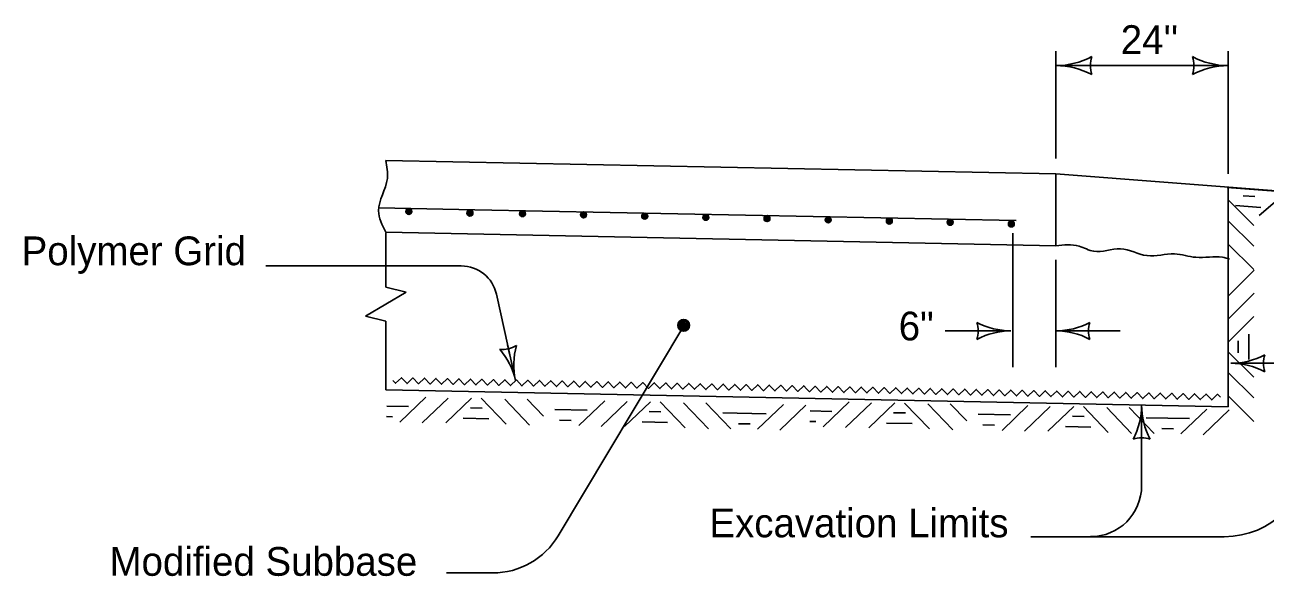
# Model space of a CAD drawing. Extents: x 5546 to 81668, y 3174 to 15999.
# Drawn here: x 17301 to 17992, y 13163 to 13470 of the extents above; entities that cross this region are included whole.
import ezdxf

# ---------------------------------------------------------------- set-up
doc = ezdxf.new("R2010")
doc.units = 0
for name, color, linetype in [('PS_CONST', 7, 'Continuous'), ('PS_DAWA', 7, 'Continuous'), ('PS_DIM', 7, 'Continuous')]:
    doc.layers.add(name, color=color, linetype=linetype)

msp = doc.modelspace()

# ---------------------------------------------------------------- linework, layer by layer
at = {"layer": 'PS_CONST'}
for p, q in [((17435.53, 13335.55), (17544.32, 13335.55)), ((17563.85, 13319.86), (17574.46, 13271.73)), ((17598.32, 13185.41), (17668.13, 13302.18)), ((17997.4, 13281.41), (17972.68, 13281.41)), ((17923, 13258.09), (17923, 13213.24)), ((17969.04, 13184.87), (17861.27, 13184.87)), ((17536.04, 13164.7), (17561.8, 13164.7))]:
    msp.add_line(p, q, dxfattribs=at)
msp.add_lwpolyline([(17667.85, 13299.47), (17668.97, 13299.97), (17670.7, 13300.51), (17671.04, 13302.27), (17670.8, 13303.82), (17669.69, 13305.25), (17668.04, 13305.1), (17666.3, 13304.85), (17665.46, 13303.47), (17665.31, 13302), (17666.33, 13300.09), (17667.61, 13299.93), (17669.34, 13300.37), (17670.77, 13301.48), (17670.73, 13303.14), (17669.61, 13304.47), (17668.05, 13304.61), (17666.31, 13304.27), (17666.05, 13303.29), (17665.7, 13302.11), (17666.51, 13300.68), (17667.78, 13300.72), (17669.23, 13300.95), (17670.28, 13301.76), (17669.75, 13303.2), (17668.65, 13304.05), (17667.19, 13304.1), (17666.83, 13303.32), (17666.36, 13302.43), (17667.08, 13301.28), (17668.16, 13301.02), (17669.12, 13301.53), (17669.18, 13302.6), (17668.68, 13303.37), (17667.69, 13303.63), (17667.22, 13303.23), (17666.94, 13302.64), (17667.45, 13301.78), (17668.14, 13301.6), (17668.81, 13302.01), (17668.7, 13302.59), (17668.2, 13302.96), (17667.52, 13302.94), (17667.53, 13302.46), (17668.13, 13302.18)], dxfattribs=at)
msp.add_circle((17668.11, 13302.51), 3.31, dxfattribs=at)
for centre, radius, start, end in [((17544.32, 13315.55), 20, 12.43134, 90), ((17567.22, 13304.63), 15.52, 264.68499, 300.15169), ((17613.7, 13280.37), 40.18, 164.34585, 192.41834), ((17535.23, 13263.09), 40.18, 12.41834, 40.49083), ((17972.68, 13321.58), 40.18, 270, 298.07249), ((18006.37, 13281.41), 15.52, 162.26665, 197.73335), ((17972.68, 13241.23), 40.18, 61.92751, 90), ((17882.82, 13258.09), 40.18, 331.92751, 360), ((17963.17, 13258.09), 40.18, 180, 208.07249), ((17923, 13224.41), 15.52, 72.26665, 107.73335), ((17969.04, 13232.14), 47.27, 270, 360), ((17894.64, 13213.24), 28.36, 270, 360), ((17561.8, 13207.24), 42.54, 270, 329.12488)]:
    msp.add_arc(centre, radius, start, end, dxfattribs=at)
at = {"layer": 'PS_DAWA'}
for p, q in [((17875.27, 13395.36), (17875.27, 13455.07)), ((17971.27, 13386.8), (17971.27, 13455.07)), ((17875.27, 13447.09), (17971.27, 13447.09)), ((17851.27, 13279.25), (17851.27, 13353.72)), ((17875.27, 13279.25), (17875.27, 13338.95)), ((17850.28, 13299.44), (17813.74, 13299.44)), ((17911.05, 13299.44), (17875.27, 13299.44))]:
    msp.add_line(p, q, dxfattribs=at)
for centre, radius, start, end in [((17875.27, 13489.59), 42.5, 270, 298.07249), ((17910.9, 13447.09), 16.42, 162.26665, 197.73335), ((17935.63, 13447.09), 16.42, 342.26665, 17.73335), ((17971.27, 13489.59), 42.5, 241.92751, 270), ((17875.27, 13404.59), 42.5, 61.92751, 90), ((17971.27, 13404.59), 42.5, 90, 118.07249), ((17816.59, 13299.43), 15.52, 342.26665, 17.73335), ((17850.28, 13339.61), 40.18, 241.92751, 270), ((17850.28, 13259.26), 40.18, 90, 118.07249), ((17875.27, 13339.61), 40.18, 270, 298.07249), ((17875.27, 13259.26), 40.18, 61.92751, 90), ((17908.95, 13299.44), 15.52, 162.26665, 197.73335)]:
    msp.add_arc(centre, radius, start, end, dxfattribs=at)
at = {"layer": 'PS_DIM'}
for p, q in [((17875.27, 13386.8), (17502.34, 13394.29)), ((17502.34, 13394.29), (17875.27, 13386.8)), ((17875.27, 13346.79), (17875.27, 13386.8)), ((17875.27, 13386.8), (17875.27, 13346.79)), ((17875.27, 13386.8), (18074.73, 13371.45)), ((17970.65, 13379.22), (18074.12, 13371.26)), ((17971.27, 13257.15), (17971.27, 13379.41)), ((18003.56, 13376.69), (17988.38, 13363.67)), ((17551.81, 13366.85), (17498.37, 13367.92)), ((17853.17, 13360.8), (17551.81, 13366.85)), ((17971.27, 13372.31), (17985.41, 13358.16)), ((17971.27, 13360.73), (17985.41, 13346.59)), ((17502.34, 13354.28), (17875.27, 13346.79)), ((17502.34, 13354.28), (17875.27, 13346.79)), ((17502.34, 13354.02), (17502.34, 13323.76)), ((17971.27, 13347.67), (17985.41, 13333.53)), ((17971.49, 13319.14), (17985.64, 13333.28)), ((17502.34, 13323.76), (17513.68, 13320.92)), ((17513.68, 13320.92), (17502.34, 13314.31)), ((17971.49, 13306.23), (17985.64, 13320.38)), ((17502.34, 13314.31), (17490.99, 13307.69)), ((17490.99, 13307.69), (17502.34, 13304.85)), ((17502.34, 13304.85), (17502.34, 13266.54)), ((17971.27, 13293.23), (17985.41, 13307.37)), ((17570.07, 13291.65), (17571.2, 13286.54)), ((17971.27, 13287.81), (17985.41, 13273.67)), ((17971.27, 13276.24), (17985.41, 13262.1)), ((17502.34, 13266.54), (17971.26, 13257.12)), ((17971.27, 13263.18), (17985.41, 13249.04)), ((17524.61, 13262.52), (17510.19, 13248.67)), ((17537.05, 13262.04), (17522.63, 13248.19)), ((17550.06, 13262.01), (17535.64, 13248.15)), ((17555.47, 13261.9), (17569.33, 13247.48)), ((17568.47, 13261.41), (17582.33, 13246.99)), ((17580.93, 13261.39), (17590.03, 13251.92)), ((17624.14, 13260.52), (17609.72, 13246.67)), ((17636.58, 13260.05), (17622.16, 13246.19)), ((17649.59, 13260.01), (17635.17, 13246.16)), ((17655, 13259.9), (17668.86, 13245.48)), ((17668.01, 13259.42), (17681.86, 13244.99)), ((17680.46, 13259.39), (17694.31, 13244.97)), ((17723.67, 13258.53), (17709.25, 13244.67)), ((17736.12, 13258.05), (17721.69, 13244.19)), ((17760.21, 13259.88), (17745.79, 13246.03)), ((17772.65, 13259.41), (17758.23, 13245.55)), ((17785.66, 13259.37), (17771.24, 13245.52)), ((17791.07, 13259.26), (17804.93, 13244.84)), ((17804.08, 13258.78), (17817.93, 13244.35)), ((17816.53, 13258.75), (17825.63, 13249.28)), ((17859.74, 13257.89), (17845.32, 13244.03)), ((17872.19, 13257.41), (17857.76, 13243.55)), ((17885.2, 13257.38), (17870.77, 13243.52)), ((17890.61, 13257.27), (17904.46, 13242.84)), ((17903.61, 13256.78), (17917.46, 13242.36)), ((17916.06, 13256.76), (17929.92, 13242.33)), ((17959.28, 13255.89), (17944.85, 13242.03)), ((17971.72, 13255.41), (17957.3, 13241.56))]:
    msp.add_line(p, q, dxfattribs=at)
for points in [[(17979.57, 13374.68), (17986.09, 13374.18)], [(17513.59, 13365.79), (17513.84, 13366.36), (17514.11, 13367.22), (17514.99, 13367.39), (17515.76, 13367.27), (17516.48, 13366.71), (17516.4, 13365.89), (17516.28, 13365.02), (17515.59, 13364.6), (17514.86, 13364.52), (17513.9, 13365.04), (17513.82, 13365.67), (17514.04, 13366.54), (17514.6, 13367.26), (17515.42, 13367.23), (17516.09, 13366.68), (17516.16, 13365.9), (17515.99, 13365.03), (17515.5, 13364.89), (17514.91, 13364.72), (17514.19, 13365.12), (17514.21, 13365.76), (17514.33, 13366.48), (17514.73, 13367.01), (17515.46, 13366.74), (17515.88, 13366.2), (17515.9, 13365.47), (17515.51, 13365.28), (17515.07, 13365.05), (17514.49, 13365.41), (17514.36, 13365.95), (17514.62, 13366.43), (17515.16, 13366.46), (17515.54, 13366.21), (17515.67, 13365.71), (17515.47, 13365.48), (17515.17, 13365.34), (17514.74, 13365.59), (17514.66, 13365.94), (17514.86, 13366.27), (17515.15, 13366.22), (17515.34, 13365.97), (17515.33, 13365.63), (17515.08, 13365.63), (17514.95, 13365.93)], [(17547.62, 13364.87), (17547.87, 13365.42), (17548.14, 13366.3), (17549.02, 13366.46), (17549.79, 13366.34), (17550.51, 13365.79), (17550.44, 13364.96), (17550.31, 13364.09), (17549.62, 13363.67), (17548.89, 13363.59), (17547.93, 13364.11), (17547.85, 13364.74), (17548.07, 13365.62), (17548.63, 13366.32), (17549.45, 13366.3), (17550.12, 13365.75), (17550.19, 13364.97), (17550.02, 13364.1), (17549.53, 13363.97), (17548.94, 13363.79), (17548.23, 13364.2), (17548.24, 13364.83), (17548.36, 13365.56), (17548.77, 13366.08), (17549.49, 13365.82), (17549.91, 13365.27), (17549.94, 13364.54), (17549.54, 13364.35), (17549.1, 13364.12), (17548.52, 13364.48), (17548.4, 13365.02), (17548.65, 13365.5), (17549.19, 13365.53), (17549.57, 13365.28), (17549.7, 13364.79), (17549.5, 13364.55), (17549.2, 13364.41), (17548.77, 13364.67), (17548.69, 13365.01), (17548.89, 13365.35), (17549.18, 13365.29), (17549.37, 13365.04), (17549.36, 13364.7), (17549.11, 13364.7), (17548.98, 13365)], [(17975.3, 13369.13), (17989.45, 13368.04)], [(17579.88, 13364.53), (17579.63, 13365.1), (17579.36, 13365.96), (17578.48, 13366.13), (17577.71, 13366.01), (17576.99, 13365.45), (17577.06, 13364.63), (17577.18, 13363.76), (17577.88, 13363.34), (17578.61, 13363.26), (17579.57, 13363.78), (17579.65, 13364.42), (17579.43, 13365.28), (17578.87, 13366), (17578.05, 13365.97), (17577.38, 13365.42), (17577.31, 13364.64), (17577.47, 13363.77), (17577.97, 13363.63), (17578.56, 13363.46), (17579.27, 13363.87), (17579.26, 13364.5), (17579.14, 13365.23), (17578.73, 13365.75), (17578.01, 13365.48), (17577.59, 13364.94), (17577.56, 13364.21), (17577.96, 13364.02), (17578.4, 13363.8), (17578.98, 13364.15), (17579.1, 13364.69), (17578.85, 13365.17), (17578.31, 13365.2), (17577.93, 13364.95), (17577.8, 13364.46), (17578, 13364.22), (17578.3, 13364.08), (17578.72, 13364.34), (17578.81, 13364.68), (17578.61, 13365.02), (17578.32, 13364.96), (17578.13, 13364.71), (17578.14, 13364.37), (17578.39, 13364.38), (17578.52, 13364.67)], [(17613.91, 13363.86), (17613.66, 13364.41), (17613.39, 13365.28), (17612.51, 13365.45), (17611.74, 13365.33), (17611.02, 13364.77), (17611.1, 13363.95), (17611.21, 13363.08), (17611.91, 13362.66), (17612.64, 13362.58), (17613.6, 13363.09), (17613.68, 13363.73), (17613.46, 13364.6), (17612.9, 13365.32), (17612.08, 13365.29), (17611.41, 13364.74), (17611.34, 13363.95), (17611.51, 13363.09), (17612, 13362.95), (17612.59, 13362.78), (17613.31, 13363.18), (17613.28, 13363.82), (17613.17, 13364.54), (17612.77, 13365.07), (17612.04, 13364.8), (17611.62, 13364.25), (17611.59, 13363.52), (17611.98, 13363.34), (17612.43, 13363.11), (17613.01, 13363.47), (17613.13, 13364.01), (17612.88, 13364.49), (17612.34, 13364.52), (17611.96, 13364.27), (17611.83, 13363.77), (17612.03, 13363.54), (17612.33, 13363.4), (17612.76, 13363.65), (17612.84, 13364), (17612.64, 13364.33), (17612.35, 13364.28), (17612.16, 13364.03), (17612.17, 13363.69), (17612.42, 13363.69), (17612.55, 13363.99)], [(17647.94, 13363.17), (17647.69, 13363.73), (17647.42, 13364.6), (17646.54, 13364.77), (17645.77, 13364.65), (17645.05, 13364.09), (17645.13, 13363.26), (17645.25, 13362.39), (17645.94, 13361.97), (17646.67, 13361.9), (17647.63, 13362.41), (17647.71, 13363.05), (17647.49, 13363.92), (17646.94, 13364.63), (17646.11, 13364.61), (17645.44, 13364.05), (17645.37, 13363.27), (17645.54, 13362.4), (17646.03, 13362.27), (17646.62, 13362.09), (17647.34, 13362.5), (17647.32, 13363.13), (17647.2, 13363.86), (17646.8, 13364.39), (17646.08, 13364.12), (17645.65, 13363.57), (17645.63, 13362.84), (17646.02, 13362.66), (17646.47, 13362.43), (17647.04, 13362.79), (17647.17, 13363.33), (17646.91, 13363.8), (17646.38, 13363.84), (17645.99, 13363.58), (17645.86, 13363.09), (17646.06, 13362.85), (17646.36, 13362.72), (17646.79, 13362.97), (17646.88, 13363.32), (17646.67, 13363.65), (17646.38, 13363.59), (17646.2, 13363.35), (17646.2, 13363), (17646.45, 13363.01), (17646.58, 13363.31)], [(17681.98, 13362.49), (17681.72, 13363.04), (17681.46, 13363.91), (17680.58, 13364.08), (17679.8, 13363.96), (17679.09, 13363.41), (17679.16, 13362.58), (17679.28, 13361.71), (17679.97, 13361.29), (17680.71, 13361.21), (17681.66, 13361.73), (17681.75, 13362.36), (17681.52, 13363.24), (17680.97, 13363.95), (17680.14, 13363.92), (17679.48, 13363.37), (17679.4, 13362.59), (17679.57, 13361.72), (17680.07, 13361.58), (17680.65, 13361.41), (17681.37, 13361.82), (17681.35, 13362.45), (17681.24, 13363.18), (17680.83, 13363.7), (17680.11, 13363.44), (17679.68, 13362.89), (17679.66, 13362.16), (17680.05, 13361.97), (17680.5, 13361.74), (17681.07, 13362.1), (17681.2, 13362.64), (17680.95, 13363.12), (17680.41, 13363.15), (17680.03, 13362.9), (17679.89, 13362.41), (17680.09, 13362.17), (17680.39, 13362.03), (17680.82, 13362.29), (17680.91, 13362.63), (17680.71, 13362.97), (17680.42, 13362.91), (17680.23, 13362.66), (17680.24, 13362.32), (17680.48, 13362.33), (17680.62, 13362.62)], [(17716.01, 13361.8), (17715.76, 13362.36), (17715.49, 13363.23), (17714.61, 13363.4), (17713.84, 13363.28), (17713.12, 13362.72), (17713.19, 13361.9), (17713.32, 13361.02), (17714.01, 13360.61), (17714.74, 13360.53), (17715.7, 13361.05), (17715.78, 13361.68), (17715.56, 13362.55), (17715, 13363.26), (17714.18, 13363.24), (17713.51, 13362.68), (17713.44, 13361.91), (17713.6, 13361.03), (17714.1, 13360.9), (17714.69, 13360.73), (17715.4, 13361.14), (17715.39, 13361.76), (17715.27, 13362.5), (17714.86, 13363.02), (17714.14, 13362.75), (17713.72, 13362.2), (17713.69, 13361.47), (17714.09, 13361.29), (17714.53, 13361.06), (17715.11, 13361.42), (17715.23, 13361.96), (17714.98, 13362.44), (17714.44, 13362.47), (17714.06, 13362.22), (17713.93, 13361.73), (17714.13, 13361.49), (17714.43, 13361.35), (17714.86, 13361.61), (17714.94, 13361.95), (17714.74, 13362.28), (17714.45, 13362.23), (17714.26, 13361.98), (17714.27, 13361.64), (17714.52, 13361.64), (17714.65, 13361.94)], [(17750.04, 13361.12), (17749.79, 13361.68), (17749.52, 13362.55), (17748.64, 13362.72), (17747.87, 13362.6), (17747.15, 13362.04), (17747.23, 13361.21), (17747.35, 13360.34), (17748.04, 13359.93), (17748.77, 13359.85), (17749.73, 13360.36), (17749.81, 13361), (17749.59, 13361.87), (17749.03, 13362.58), (17748.21, 13362.56), (17747.54, 13362), (17747.47, 13361.22), (17747.64, 13360.35), (17748.13, 13360.22), (17748.72, 13360.04), (17749.44, 13360.45), (17749.42, 13361.08), (17749.3, 13361.81), (17748.9, 13362.34), (17748.17, 13362.07), (17747.75, 13361.52), (17747.73, 13360.79), (17748.12, 13360.61), (17748.56, 13360.38), (17749.14, 13360.73), (17749.26, 13361.27), (17749.01, 13361.76), (17748.47, 13361.79), (17748.09, 13361.53), (17747.96, 13361.04), (17748.16, 13360.8), (17748.46, 13360.67), (17748.89, 13360.92), (17748.97, 13361.27), (17748.77, 13361.6), (17748.48, 13361.54), (17748.29, 13361.29), (17748.3, 13360.96), (17748.55, 13360.96), (17748.68, 13361.26)], [(17784.07, 13360.44), (17783.82, 13360.99), (17783.55, 13361.86), (17782.67, 13362.03), (17781.9, 13361.91), (17781.18, 13361.36), (17781.26, 13360.53), (17781.38, 13359.66), (17782.07, 13359.24), (17782.8, 13359.16), (17783.76, 13359.68), (17783.84, 13360.31), (17783.62, 13361.19), (17783.07, 13361.9), (17782.24, 13361.88), (17781.58, 13361.32), (17781.5, 13360.54), (17781.67, 13359.67), (17782.16, 13359.54), (17782.75, 13359.36), (17783.47, 13359.77), (17783.45, 13360.4), (17783.33, 13361.13), (17782.93, 13361.65), (17782.21, 13361.39), (17781.78, 13360.84), (17781.76, 13360.11), (17782.15, 13359.93), (17782.6, 13359.69), (17783.17, 13360.05), (17783.3, 13360.59), (17783.04, 13361.07), (17782.51, 13361.11), (17782.12, 13360.85), (17781.99, 13360.36), (17782.19, 13360.12), (17782.49, 13359.98), (17782.92, 13360.24), (17783.01, 13360.58), (17782.8, 13360.92), (17782.51, 13360.86), (17782.33, 13360.61), (17782.33, 13360.27), (17782.58, 13360.28), (17782.71, 13360.58)], [(17814.95, 13359.75), (17815.2, 13360.31), (17815.47, 13361.17), (17816.35, 13361.34), (17817.12, 13361.22), (17817.84, 13360.67), (17817.76, 13359.84), (17817.64, 13358.97), (17816.95, 13358.55), (17816.22, 13358.47), (17815.26, 13358.99), (17815.18, 13359.62), (17815.4, 13360.49), (17815.96, 13361.21), (17816.78, 13361.18), (17817.45, 13360.63), (17817.52, 13359.85), (17817.35, 13358.98), (17816.86, 13358.84), (17816.27, 13358.67), (17815.55, 13359.07), (17815.57, 13359.71), (17815.69, 13360.43), (17816.09, 13360.96), (17816.81, 13360.7), (17817.24, 13360.15), (17817.26, 13359.42), (17816.87, 13359.23), (17816.43, 13359), (17815.85, 13359.36), (17815.72, 13359.9), (17815.98, 13360.38), (17816.52, 13360.41), (17816.9, 13360.16), (17817.03, 13359.67), (17816.83, 13359.43), (17816.53, 13359.29), (17816.1, 13359.55), (17816.02, 13359.89), (17816.22, 13360.22), (17816.51, 13360.17), (17816.69, 13359.92), (17816.68, 13359.58), (17816.44, 13359.59), (17816.31, 13359.88)], [(17848.98, 13358.82), (17849.23, 13359.38), (17849.5, 13360.25), (17850.38, 13360.41), (17851.15, 13360.29), (17851.87, 13359.74), (17851.8, 13358.91), (17851.67, 13358.04), (17850.98, 13357.62), (17850.25, 13357.54), (17849.29, 13358.06), (17849.21, 13358.69), (17849.43, 13359.57), (17849.99, 13360.28), (17850.81, 13360.25), (17851.48, 13359.7), (17851.55, 13358.92), (17851.38, 13358.05), (17850.89, 13357.92), (17850.3, 13357.74), (17849.58, 13358.15), (17849.6, 13358.78), (17849.72, 13359.51), (17850.13, 13360.03), (17850.85, 13359.77), (17851.27, 13359.22), (17851.3, 13358.49), (17850.9, 13358.31), (17850.46, 13358.07), (17849.88, 13358.43), (17849.76, 13358.97), (17850.01, 13359.45), (17850.55, 13359.48), (17850.93, 13359.23), (17851.06, 13358.74), (17850.86, 13358.5), (17850.56, 13358.36), (17850.13, 13358.62), (17850.05, 13358.96), (17850.25, 13359.3), (17850.54, 13359.24), (17850.73, 13358.99), (17850.72, 13358.65), (17850.47, 13358.66), (17850.34, 13358.95)], [(17982.62, 13283.42), (17982.62, 13297.62)], [(17976.77, 13287.25), (17976.77, 13293.79)], [(17506.15, 13271.87), (17507.72, 13270.23), (17510.98, 13273.37), (17514.12, 13270.11), (17517.38, 13273.24), (17520.52, 13269.98), (17523.78, 13273.11), (17526.91, 13269.85), (17530.18, 13272.98), (17533.31, 13269.72), (17536.58, 13272.86), (17539.71, 13269.59), (17542.98, 13272.73), (17546.11, 13269.46), (17549.37, 13272.6), (17552.51, 13269.34), (17555.77, 13272.47), (17558.91, 13269.21), (17562.17, 13272.34), (17565.31, 13269.08), (17568.57, 13272.21), (17571.71, 13268.95), (17574.97, 13272.09), (17578.1, 13268.82), (17581.37, 13271.96), (17582.94, 13270.33)], [(17582.94, 13270.33), (17584.5, 13268.69), (17587.77, 13271.83), (17590.9, 13268.56), (17594.16, 13271.7), (17597.3, 13268.44), (17600.56, 13271.57), (17603.7, 13268.31), (17606.96, 13271.44), (17610.1, 13268.18), (17613.36, 13271.31), (17616.5, 13268.05), (17619.76, 13271.19), (17622.89, 13267.92), (17626.16, 13271.06), (17629.29, 13267.79), (17632.56, 13270.93), (17635.69, 13267.67), (17638.96, 13270.8), (17642.09, 13267.54), (17645.35, 13270.67), (17648.49, 13267.41), (17651.75, 13270.54), (17654.89, 13267.28), (17658.15, 13270.42), (17659.72, 13268.78)], [(17659.72, 13268.78), (17661.29, 13267.15), (17664.55, 13270.29), (17667.69, 13267.02), (17670.95, 13270.16), (17674.08, 13266.9), (17677.35, 13270.03), (17680.48, 13266.77), (17683.75, 13269.9), (17686.88, 13266.64), (17690.15, 13269.77), (17693.28, 13266.51), (17696.54, 13269.64), (17699.68, 13266.38), (17702.94, 13269.52), (17706.08, 13266.25), (17709.34, 13269.39), (17712.48, 13266.12), (17715.74, 13269.26), (17718.88, 13266), (17722.14, 13269.13), (17725.27, 13265.87), (17728.54, 13269), (17731.67, 13265.74), (17734.94, 13268.87), (17736.5, 13267.24)], [(17736.54, 13267.14), (17738.11, 13265.51), (17741.37, 13268.64), (17744.5, 13265.38), (17747.77, 13268.52), (17750.9, 13265.25), (17754.17, 13268.39), (17757.3, 13265.12), (17760.57, 13268.26), (17763.7, 13265), (17766.96, 13268.13), (17770.1, 13264.87), (17773.36, 13268), (17776.5, 13264.74), (17779.76, 13267.87), (17782.9, 13264.61), (17786.16, 13267.75), (17789.3, 13264.48), (17792.56, 13267.62), (17795.69, 13264.35), (17798.96, 13267.49), (17802.09, 13264.23), (17805.36, 13267.36), (17808.49, 13264.1), (17811.76, 13267.23), (17813.32, 13265.6)], [(17813.32, 13265.6), (17814.89, 13263.97), (17818.15, 13267.1), (17821.29, 13263.84), (17824.55, 13266.98), (17827.69, 13263.71), (17830.95, 13266.85), (17834.09, 13263.58), (17837.35, 13266.72), (17840.49, 13263.45), (17843.75, 13266.59), (17846.88, 13263.33), (17850.15, 13266.46), (17853.28, 13263.2), (17856.55, 13266.33), (17859.68, 13263.07), (17862.95, 13266.2), (17866.08, 13262.94), (17869.34, 13266.08), (17872.48, 13262.81), (17875.74, 13265.95), (17878.88, 13262.68), (17882.14, 13265.82), (17885.28, 13262.56), (17888.54, 13265.69), (17890.11, 13264.06)], [(17890.11, 13264.06), (17891.68, 13262.43), (17894.94, 13265.56), (17898.07, 13262.3), (17901.34, 13265.43), (17904.47, 13262.17), (17907.74, 13265.31), (17910.87, 13262.04), (17914.13, 13265.18), (17917.27, 13261.91), (17920.53, 13265.05), (17923.67, 13261.78), (17926.93, 13264.92), (17930.07, 13261.66), (17933.33, 13264.79), (17936.47, 13261.53), (17939.73, 13264.66), (17942.86, 13261.4), (17946.13, 13264.53), (17949.26, 13261.27), (17952.53, 13264.41), (17955.66, 13261.14), (17958.93, 13264.28), (17962.06, 13261.01), (17965.32, 13264.15), (17966.89, 13262.52)], [(17502.89, 13257.48), (17514.92, 13257.24)], [(17549.39, 13256.52), (17555.92, 13256.39)], [(17502.77, 13251.68), (17506.04, 13251.62)], [(17545.44, 13250.75), (17559.63, 13250.46)], [(17596.39, 13255.6), (17614.45, 13255.24)], [(17599.04, 13249.75), (17605.57, 13249.62)], [(17648.92, 13254.53), (17655.46, 13254.4)], [(17689.93, 13253.73), (17713.98, 13253.24)], [(17738.49, 13254.84), (17750.52, 13254.6)], [(17784.99, 13253.89), (17791.53, 13253.76)], [(17831.99, 13252.97), (17850.05, 13252.6)], [(17884.53, 13251.89), (17891.06, 13251.76)], [(17925.53, 13251.09), (17949.59, 13250.61)], [(17644.98, 13248.75), (17659.17, 13248.46)], [(17698.57, 13247.75), (17705.1, 13247.62)], [(17738.38, 13249.05), (17741.64, 13248.98)], [(17781.05, 13248.11), (17795.24, 13247.82)], [(17834.64, 13247.11), (17841.17, 13246.98)], [(17880.58, 13246.11), (17894.77, 13245.83)], [(17934.18, 13245.12), (17940.71, 13244.98)]]:
    msp.add_lwpolyline(points, dxfattribs=at)
for centre in [(17515.1, 13365.92), (17549.14, 13364.99), (17578.36, 13364.66), (17612.39, 13363.98), (17646.42, 13363.29), (17680.46, 13362.61), (17714.49, 13361.93), (17748.52, 13361.24), (17782.56, 13360.56), (17816.46, 13359.87), (17850.5, 13358.94)]:
    msp.add_circle(centre, 1.65, dxfattribs=at)
for points in [[(17502.34, 13394.29), (17503.16, 13384.27), (17498.28, 13366.23), (17502.34, 13354.28)], [(17502.34, 13394.29), (17503.16, 13384.27), (17498.28, 13366.23), (17502.34, 13354.28)], [(17875.27, 13346.79), (17888.22, 13346.58), (17896.35, 13343.71), (17911.17, 13345.15), (17926, 13341.32), (17941.3, 13342.28), (17953.26, 13340.37), (17968.08, 13340.37), (17971.91, 13339.41)]]:
    msp.add_spline(points, degree=3, dxfattribs=at)

# ---------------------------------------------------------------- texts
at = {"layer": 'PS_CONST'}
for s, p in [('Polymer Grid', (17299.62, 13335.97)), ('Excavation Limits', (17682.44, 13184.51)), ('Modified Subbase', (17348.53, 13163.1))]:
    msp.add_text(s, height=16, dxfattribs=at).set_placement(p)
at = {"layer": 'PS_DAWA'}
for s, p in [("24''", (17911.4, 13453.55)), ('6"', (17787.8, 13294.12))]:
    msp.add_text(s, height=16, dxfattribs=at).set_placement(p)

doc.saveas('drawing.dxf')
